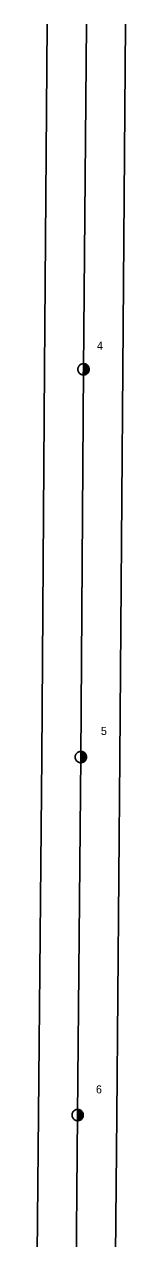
# Model space of a CAD drawing. Extents: x -762349 to -761250, y -1154000 to -1153000.
# Drawn here: x -762266.9 to -762246.7, y -1153263.9 to -1153000 of the extents above; entities that cross this region are included whole.
import ezdxf

# ---------------------------------------------------------------- set-up
doc = ezdxf.new("R2010")
doc.units = 0
for name, color, linetype in [('Vrstva 1', 7, 'Continuous'), ('Vrstva 13', 7, 'Continuous'), ('Vrstva 14', 7, 'Continuous'), ('Vrstva 35', 7, 'Continuous')]:
    doc.layers.add(name, color=color, linetype=linetype)

msp = doc.modelspace()

# ---------------------------------------------------------------- linework, layer by layer
at = {"layer": 'Vrstva 1'}
msp.add_lwpolyline([(-762255.21, -1153000), (-762255.83, -1153074.97), (-762256.42, -1153159.25), (-762257.11, -1153237.05), (-762257.87, -1153320.54), (-762258.42, -1153358.35)], dxfattribs=at)
at = {"layer": 'Vrstva 13'}
for points in [[(-762255.784, -1153073.752), (-762255.912, -1153073.754), (-762256.04, -1153073.77), (-762256.165, -1153073.799), (-762256.287, -1153073.84), (-762256.403, -1153073.895), (-762256.513, -1153073.961), (-762256.616, -1153074.039), (-762256.71, -1153074.126), (-762256.795, -1153074.223), (-762256.869, -1153074.329), (-762256.931, -1153074.441), (-762256.981, -1153074.559), (-762257.018, -1153074.682), (-762257.043, -1153074.808), (-762257.054, -1153074.937), (-762257.052, -1153075.065), (-762257.036, -1153075.193), (-762257.007, -1153075.318), (-762256.966, -1153075.439), (-762256.911, -1153075.556), (-762256.845, -1153075.666), (-762256.768, -1153075.769), (-762256.68, -1153075.863), (-762256.583, -1153075.948), (-762256.477, -1153076.021), (-762256.365, -1153076.083), (-762256.247, -1153076.134), (-762256.124, -1153076.171), (-762255.998, -1153076.196), (-762255.869, -1153076.207), (-762255.741, -1153076.205), (-762255.613, -1153076.189), (-762255.488, -1153076.16), (-762255.366, -1153076.118), (-762255.25, -1153076.064), (-762255.14, -1153075.998), (-762255.037, -1153075.921), (-762254.943, -1153075.833), (-762254.859, -1153075.736), (-762254.785, -1153075.63), (-762254.722, -1153075.518), (-762254.672, -1153075.4), (-762254.635, -1153075.277), (-762254.61, -1153075.15), (-762254.599, -1153075.022), (-762254.601, -1153074.894), (-762254.617, -1153074.766), (-762254.646, -1153074.641), (-762254.687, -1153074.519), (-762254.742, -1153074.403), (-762254.808, -1153074.292), (-762254.886, -1153074.189), (-762254.973, -1153074.096), (-762255.071, -1153074.012), (-762255.176, -1153073.938), (-762255.288, -1153073.875), (-762255.406, -1153073.825), (-762255.53, -1153073.788), (-762255.656, -1153073.763), (-762255.784, -1153073.752)], [(-762255.877, -1153076.21), (-762255.792, -1153073.755)], [(-762255.53, -1153076.165), (-762255.451, -1153073.882)], [(-762255.236, -1153076.002), (-762255.168, -1153074.027)], [(-762254.939, -1153075.744), (-762254.89, -1153074.324)], [(-762256.395, -1153158.031), (-762256.524, -1153158.035), (-762256.651, -1153158.053), (-762256.776, -1153158.084), (-762256.897, -1153158.128), (-762257.012, -1153158.185), (-762257.121, -1153158.253), (-762257.223, -1153158.332), (-762257.315, -1153158.421), (-762257.398, -1153158.519), (-762257.47, -1153158.626), (-762257.53, -1153158.74), (-762257.578, -1153158.859), (-762257.614, -1153158.983), (-762257.636, -1153159.109), (-762257.645, -1153159.238), (-762257.641, -1153159.366), (-762257.623, -1153159.493), (-762257.591, -1153159.618), (-762257.548, -1153159.739), (-762257.491, -1153159.855), (-762257.423, -1153159.963), (-762257.344, -1153160.065), (-762257.254, -1153160.157), (-762257.156, -1153160.24), (-762257.049, -1153160.312), (-762256.936, -1153160.372), (-762256.817, -1153160.42), (-762256.693, -1153160.456), (-762256.567, -1153160.478), (-762256.438, -1153160.487), (-762256.31, -1153160.483), (-762256.183, -1153160.465), (-762256.058, -1153160.434), (-762255.937, -1153160.389), (-762255.821, -1153160.333), (-762255.712, -1153160.265), (-762255.611, -1153160.186), (-762255.518, -1153160.097), (-762255.436, -1153159.998), (-762255.364, -1153159.892), (-762255.303, -1153159.778), (-762255.255, -1153159.659), (-762255.22, -1153159.535), (-762255.198, -1153159.408), (-762255.189, -1153159.281), (-762255.193, -1153159.152), (-762255.211, -1153159.025), (-762255.242, -1153158.9), (-762255.286, -1153158.779), (-762255.342, -1153158.664), (-762255.411, -1153158.554), (-762255.49, -1153158.453), (-762255.579, -1153158.361), (-762255.678, -1153158.278), (-762255.784, -1153158.206), (-762255.897, -1153158.146), (-762256.017, -1153158.098), (-762256.141, -1153158.062), (-762256.267, -1153158.04), (-762256.395, -1153158.031)], [(-762256.446, -1153160.491), (-762256.403, -1153158.034)], [(-762256.1, -1153160.439), (-762256.06, -1153158.155)], [(-762255.809, -1153160.271), (-762255.774, -1153158.295)], [(-762255.516, -1153160.007), (-762255.492, -1153158.588)], [(-762257.085, -1153235.831), (-762257.214, -1153235.835), (-762257.341, -1153235.853), (-762257.466, -1153235.884), (-762257.587, -1153235.928), (-762257.702, -1153235.985), (-762257.811, -1153236.053), (-762257.913, -1153236.132), (-762258.005, -1153236.221), (-762258.088, -1153236.319), (-762258.16, -1153236.426), (-762258.22, -1153236.54), (-762258.268, -1153236.659), (-762258.304, -1153236.783), (-762258.326, -1153236.909), (-762258.335, -1153237.038), (-762258.331, -1153237.166), (-762258.313, -1153237.293), (-762258.281, -1153237.418), (-762258.238, -1153237.539), (-762258.181, -1153237.655), (-762258.113, -1153237.763), (-762258.034, -1153237.865), (-762257.944, -1153237.957), (-762257.846, -1153238.04), (-762257.739, -1153238.112), (-762257.626, -1153238.172), (-762257.507, -1153238.22), (-762257.383, -1153238.256), (-762257.257, -1153238.278), (-762257.128, -1153238.287), (-762257, -1153238.283), (-762256.873, -1153238.265), (-762256.748, -1153238.234), (-762256.627, -1153238.189), (-762256.511, -1153238.133), (-762256.402, -1153238.065), (-762256.301, -1153237.986), (-762256.208, -1153237.897), (-762256.126, -1153237.798), (-762256.054, -1153237.692), (-762255.993, -1153237.578), (-762255.945, -1153237.459), (-762255.91, -1153237.335), (-762255.888, -1153237.208), (-762255.879, -1153237.081), (-762255.883, -1153236.952), (-762255.901, -1153236.825), (-762255.932, -1153236.7), (-762255.976, -1153236.579), (-762256.032, -1153236.464), (-762256.101, -1153236.354), (-762256.18, -1153236.253), (-762256.269, -1153236.161), (-762256.368, -1153236.078), (-762256.474, -1153236.006), (-762256.587, -1153235.946), (-762256.707, -1153235.898), (-762256.831, -1153235.862), (-762256.957, -1153235.84), (-762257.085, -1153235.831)], [(-762257.136, -1153238.291), (-762257.093, -1153235.834)], [(-762256.79, -1153238.239), (-762256.75, -1153235.955)], [(-762256.499, -1153238.071), (-762256.464, -1153236.095)], [(-762256.206, -1153237.807), (-762256.182, -1153236.388)]]:
    msp.add_lwpolyline(points, dxfattribs=at)
at = {"layer": 'Vrstva 35'}
msp.add_lwpolyline([(-762263.71, -1153000), (-762264.33, -1153074.91), (-762264.92, -1153159.18), (-762265.61, -1153236.97), (-762266.37, -1153320.44), (-762266.92, -1153358.23), (-762249.92, -1153358.47), (-762249.37, -1153320.64), (-762248.61, -1153237.13), (-762247.92, -1153159.32), (-762247.33, -1153075.03), (-762246.71, -1153000)], dxfattribs=at)

# ---------------------------------------------------------------- texts
at = {"layer": 'Vrstva 14'}
for s, p in [('4', (-762252.92, -1153070.71)), ('5', (-762252.05, -1153154.45)), ('6', (-762253.13, -1153232.34))]:
    msp.add_text(s, height=1.74, dxfattribs=at).set_placement(p)

doc.saveas('drawing.dxf')
